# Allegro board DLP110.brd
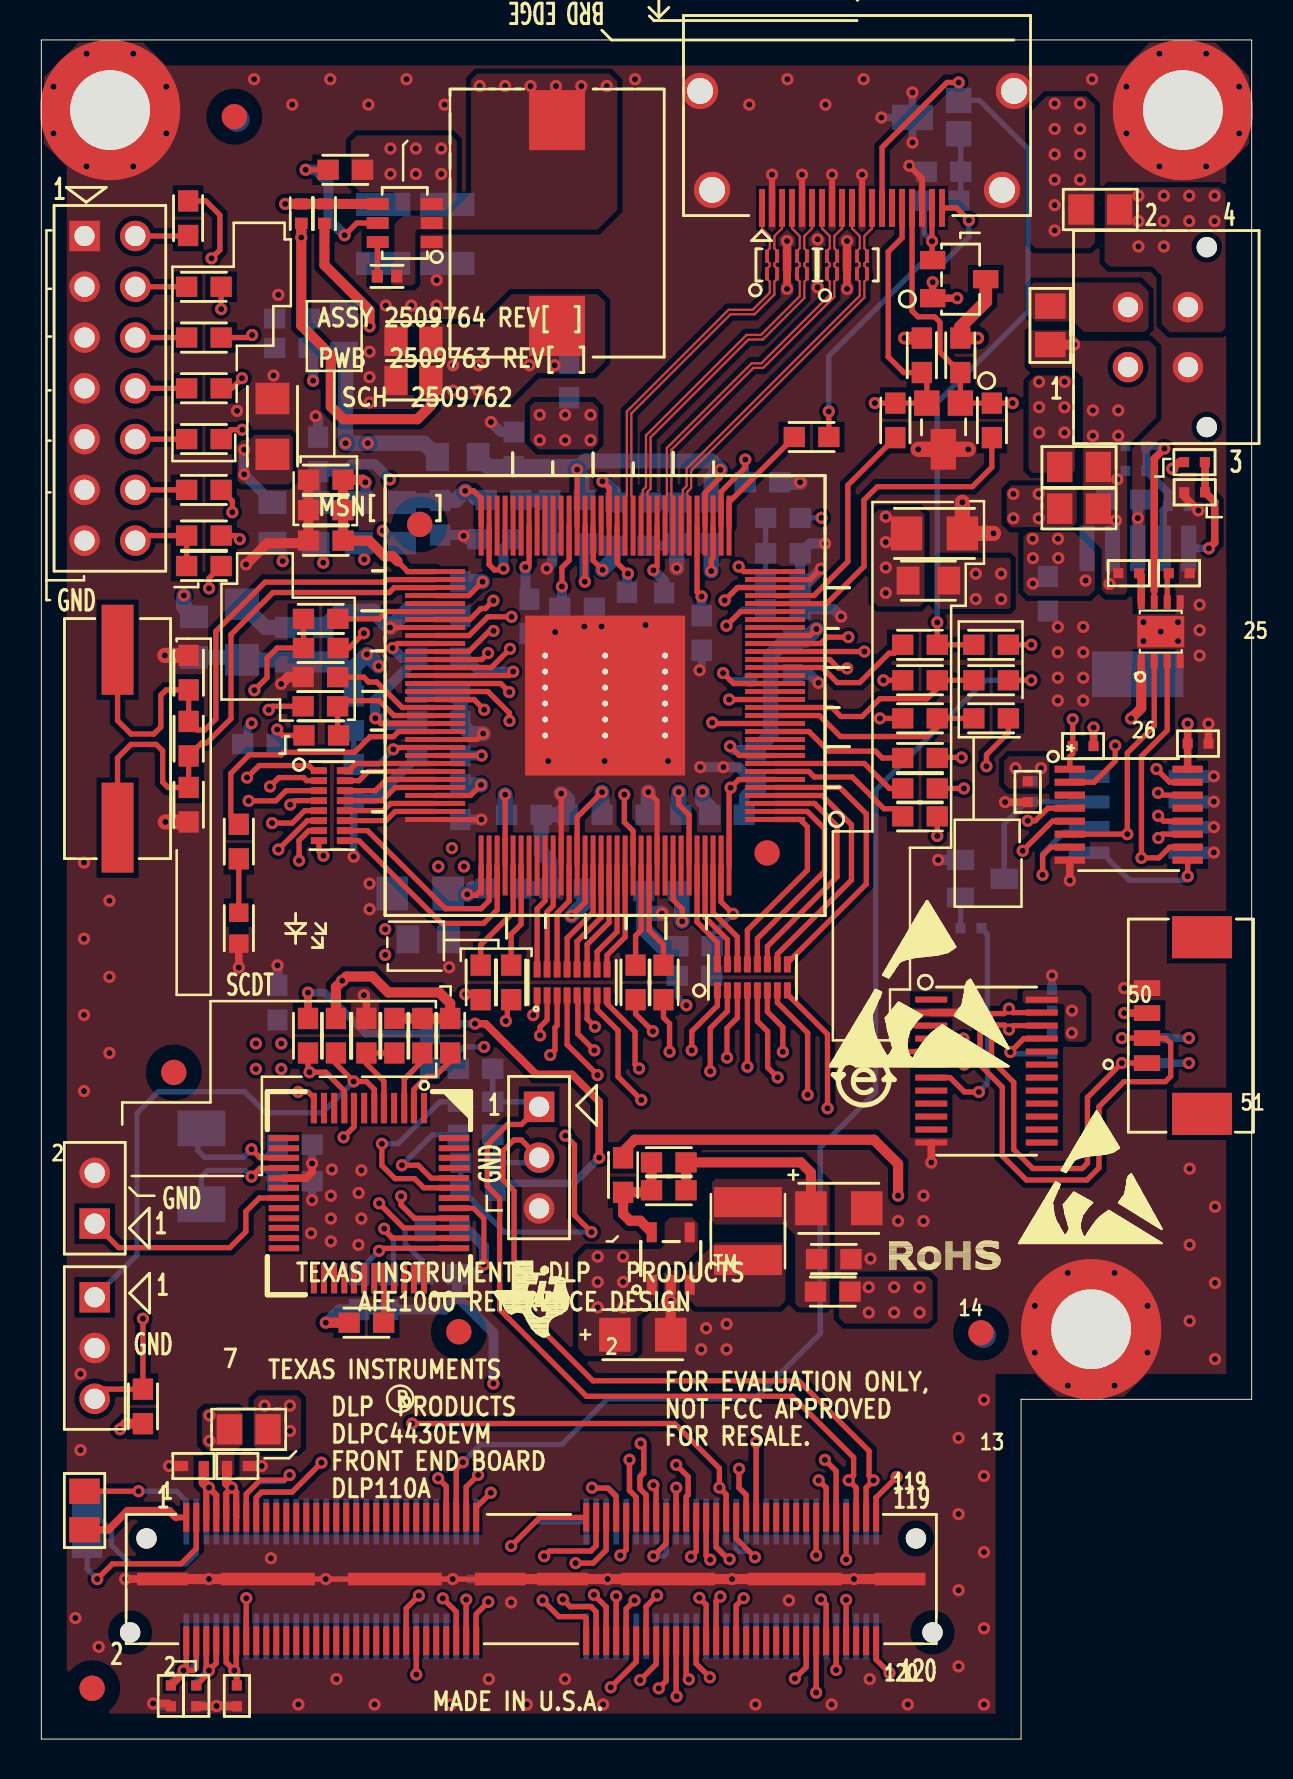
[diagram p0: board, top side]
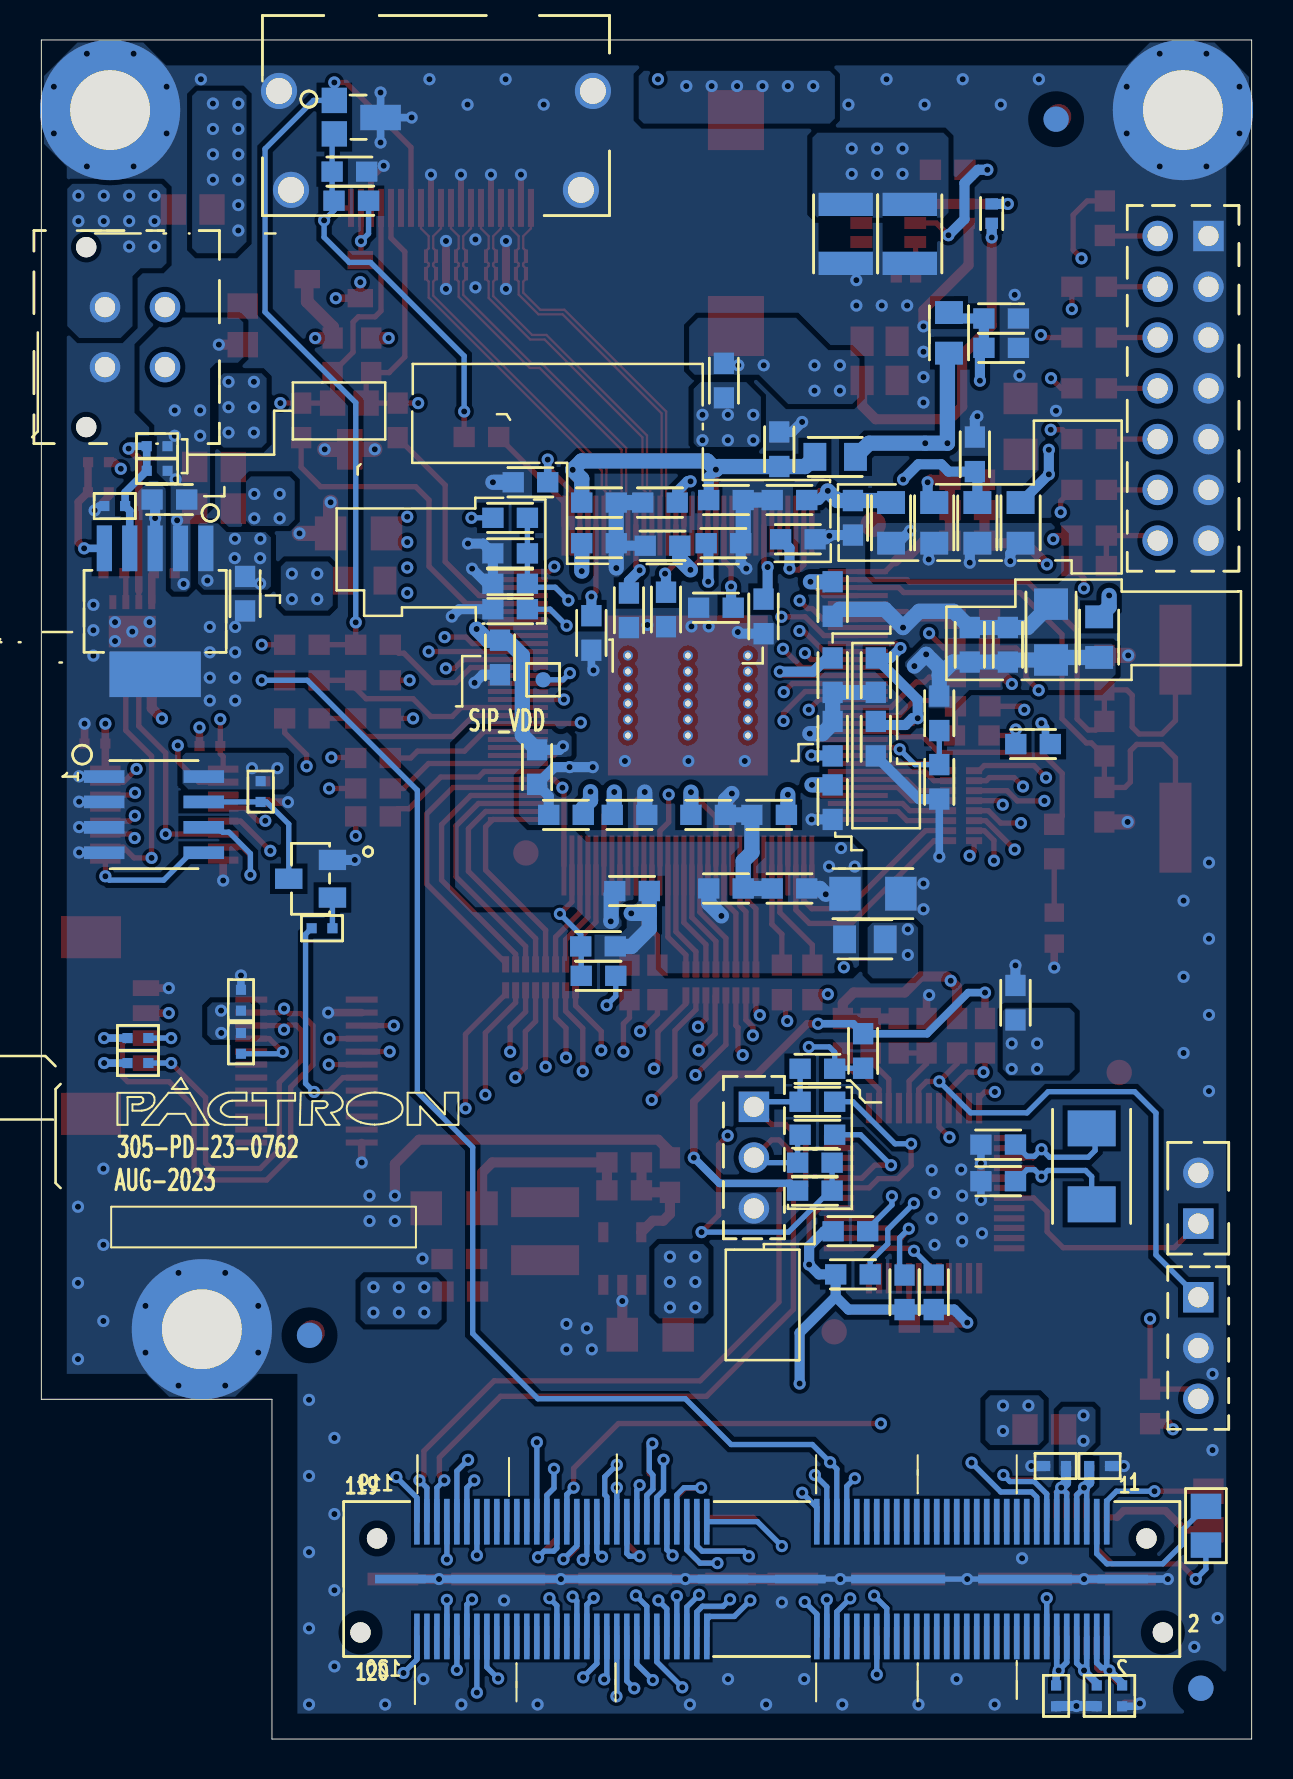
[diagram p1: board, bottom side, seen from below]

Outline 60.53 x 84.99 mm; copper layers: TOP, 02_GND1, 03_SIG1, 04_GND2, 05_SIG2, 06_PWR, 07_GND3, BOTTOM. Coordinates in mm from the lower left corner of the outline.
Outline path: 0,84.99 0,0 49,0 49,16.99 60.53,16.99 60.53,84.99 0,84.99

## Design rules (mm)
net group ALT_PWR: nets ALT_PWR ALT_PWR_MCONN
net group HSYNC: nets HSYNC P2_HSYNC
net group I2S0_DL0_CONN: nets I2S0_DL0_CONN N17213125
net group I2S1_DR1_CONN: nets I2S1_DR1_CONN N17213123
net group I2S_SCK_CONN: nets I2S_SCK_CONN N17213129
net group P1_A0: nets N17675272 P1_A0
net group P1_A1: nets N17675274 P1_A1
net group P1_B0: nets N18010978 P1_B0
net group P1_B1: nets N18010974 P1_B1
net group P1_FIELD: nets N17791476 P1_FIELD
net group P2_CLK: nets P2_CLK PCLK
net group P2_VSYNC: nets P2_VSYNC VSYNC
net group WS_DR0_CONN: nets N17213127 WS_DR0_CONN
net group CLOCK: nets N17176927 N17176943 XTAL1 XTAL2
net group GROUP_A: nets P1_ACTDATA
net group GROUP_B: nets AFE_RSTZ HAPS_CLK P1_HSYNC P1_VSYNC
net group HDMI: nets P1_A2 P1_A3 P1_A4 P1_A5 P1_A6 P1_A7 P1_A8 P1_A9 P1_B2 P1_B3 P1_B4 P1_B5 P1_B6 P1_B7 P1_B8 P1_B9 P1_C0 P1_C1 P1_C2 P1_C3 P1_C4 P1_C5 P1_C6 P1_C7 P1_C8 P1_C9
net group P1_A2: nets N17675276
net group P1_A3: nets N17675278
net group P1_A4: nets N17675280
net group P1_A5: nets N17675282
net group P1_A6: nets N17675284
net group P1_A7: nets N17675286
net group P1_A8: nets N17675288
net group P1_A9: nets N17675290
net group P1_B2: nets N18010926
net group P1_B3: nets N18010922
net group P1_B4: nets N18011121
net group P1_B5: nets N18011123
net group P1_B6: nets N18011125
net group P1_B7: nets N18011127
net group P1_B8: nets N18011129
net group P1_B9: nets N18011131
net group P1_C0: nets N18011517
net group P1_C1: nets N18011513
net group P1_C2: nets N18011465
net group P1_C3: nets N18011461
net group P1_C4: nets N18011660
net group P1_C5: nets N18011662
net group P1_C6: nets N18011664
net group P1_C7: nets N18011666
net group P1_C8: nets N18011668
net group P1_C9: nets N18011670
net group P3P3V_AFE: nets P3P3V_AFE_ADJ_A P3P3V_AFE_FB PCA9539_PU
net group P3P3V_AFE_EN: nets P3P3V_AFE_EN
net group POWER: nets HDMI_EDID_WP P1P2V_MAIN P1P8V_MAIN P2P5V_MAIN P3P3V_MAIN
net group RX_OVDD: nets N17741544

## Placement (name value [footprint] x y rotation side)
C3  0.1 uF  [CAP_0402]  57.85 49.79 180 top
C5  0.1 uF  [CAP_0402]  50.55 36.96 270 bottom
C17  18pF  [C0603]  7.37 53.34 270 top
C18  18pF  [C0603]  7.37 46.74 90 top
C34  0.1 uF  [CAP_0402]  7.6 13.66 180 top
C35  0.1 uF  [CAP_0402]  9.8 13.66 0 top
C36  0.1 uF  [CAP_0402]  6.48 2.16 270 top
C37  0.1 uF  [CAP_0402]  7.75 2.16 270 top
C38  0.1 uF  [CAP_0402]  9.78 2.16 270 top
C508  0.1 uF  [CAP_0402]  49.33 47.38 90 top
C605  2.2 uF  [CAP_0603]  50.34 57.29 270 bottom
C606  2.2 uF  [CAP_0603]  54.12 62 0 bottom
C607  0.01uF  [CAP_0402]  54.74 64.67 180 bottom
C608  0.1 uF  [CAP_0402]  57.68 62.36 0 top
C617  0.1 uF  [CAP_0402]  9.8 13.66 0 bottom
C618  0.1 uF  [CAP_0402]  7.6 13.66 180 bottom
C619  0.1 uF  [CAP_0402]  9.78 2.16 270 bottom
C620  0.1 uF  [CAP_0402]  7.75 2.16 270 bottom
C621  0.1 uF  [CAP_0402]  6.48 2.16 270 bottom
C623  10uF  [C1206]  30.08 20.22 0 top
C624  22uF  [C1206]  39.88 26.55 0 top
C625  0.1uF  [C0603]  39.63 24.01 0 top
C626  100pF  [C0603]  31.38 28.84 0 top
C628  NC  [C0603]  32.69 39.65 180 bottom
C629  10uF_10V_1206  [C1206]  10.03 55.37 90 bottom
C630  0.1uF  [C0603]  12.19 54.74 90 bottom
C631  0.1uF  [C0603]  14.1 54.74 90 bottom
C632  0.1uF  [C0603]  34.29 46.23 0 bottom
C633  0.1uF  [C0603]  20.95 46.86 270 bottom
C634  0.1uF  [C0603]  27.18 46.23 180 bottom
C635  0.1uF  [C0603]  20.95 57.02 270 bottom
C636  0.1uF  [C0603]  20.95 50.04 90 bottom
C637  0.1uF  [C0603]  20.95 53.21 270 bottom
C638  1nF  [C0603]  24.13 46.23 0 bottom
C639  1nF  [C0603]  31.11 46.23 180 bottom
C641  2.2uF  [C0603]  12.53 71.06 180 bottom
C642  0.1uF  [C0603]  12.53 69.59 180 bottom
C643  10uF_10V_1206  [C1206]  44.67 60.31 0 top
C644  0.1uF  [C0603]  22.69 60.01 180 bottom
C645  0.1uF  [C0603]  26.79 56.59 0 bottom
C646  1nF  [C0603]  29.29 56.5 270 bottom
C647  1nF  [C0603]  24.41 56.15 270 bottom
C648  2.2uF  [C0603]  32.64 61.85 180 bottom
C649  0.1uF  [C0603]  23.62 64.52 90 bottom
C650  0.1uF  [C0603]  26.29 61.98 180 bottom
C651  10uF_10V_1206  [C1206]  11.56 65.66 90 top
C652  0.1uF  [C0603]  36.07 62.87 0 bottom
C653  0.1uF  [C0603]  29.46 59.69 0 bottom
C654  0.1uF  [C0603]  31.14 56.46 270 bottom
C655  0.1uF  [C0603]  33.02 55.33 270 bottom
C660  2.2uF  [C0603]  32.64 59.82 180 bottom
C661  0.1uF  [C0603]  26.42 59.82 180 bottom
C662  0.1uF  [C0603]  13.84 64.26 90 bottom
C663  2.2uF  [C0603]  14.22 59.94 180 top
C664  0.1uF  [C0603]  14.22 61.47 180 top
C665  0.1uF  [C0603]  14.22 62.99 180 top
C666  10uF_10V_1206  [C1206]  18.94 42.29 180 bottom
C667  0.1uF  [C0603]  18.8 53.21 270 bottom
C668  0.1uF  [C0603]  18.8 50.04 270 bottom
C669  0.1uF  [C0603]  23.11 42.55 0 bottom
C670  0.1uF  [C0603]  30.99 42.42 180 bottom
C671  0.1uF  [C0603]  26.29 42.55 180 bottom
C672  0.1uF  [C0603]  35.74 48.62 270 bottom
C673  0.1uF  [C0603]  37.59 54.1 270 bottom
C676  2.2uF  [C0603]  23.11 61.98 0 bottom
C677  0.1uF  [C0603]  19.94 61.09 270 bottom
C678  0.1uF  [C0603]  29.59 61.85 0 bottom
C679  1nF  [C0603]  37.08 57.78 0 bottom
C680  22pF  [C0603]  12.67 27.9 0 bottom
C681  0.1uF  [C0603]  17.65 35.18 270 top
C682  22pF  [C0603]  12.67 29.73 0 bottom
C683  0.1uF  [C0603]  11.81 36.83 90 bottom
C796  0.1uF  [C0402]  17.29 73.17 180 top
C797  10 uF  [C1210]  17.09 75.29 90 bottom
C798  10 uF  [C1210]  20.3 75.29 90 bottom
C799  0.1uF  [C0402]  13 76.3 90 top
C800  22 uF  [C0805]  18.61 69.92 0 top
C801  22 uF  [C0805]  18.61 67.96 0 top
CN1  -  [10029449-111RLF]  40.79 84.99 180 top
D517  RClamp0502B  [SOT-523]  45.12 66.55 180 top
D518  BAV70  [SOT23B]  45.97 73.03 270 top
D519  RClamp0502B  [SOT-523]  45.6 81.13 270 bottom
D520  NC/ LED  [LED0603]  9.87 40.56 270 top
FB1  BBPY00201209600Y00  [FB0805]  7.63 55.12 0 bottom
FB2  BBPY00201209600Y00  [FB0805]  15.14 70.34 180 bottom
FB3  BBPY00201209600Y00  [FB0805]  44.36 57.95 90 top
FB4  BBPY00201209600Y00  [FB0805]  20.83 64.14 90 bottom
FB5  BBPY00201209600Y00  [FB0805]  11.56 60.83 180 bottom
FB6  BBPY00201209600Y00  [FB0805]  13.72 60.83 180 bottom
FB7  BBPY00201209600Y00  [FB0805]  15.88 60.83 180 bottom
FB8  BBPY00201209600Y00  [FB0805]  19.34 40 90 bottom
FB9  BBPY00201209600Y00  [FB0805]  18.03 60.83 180 bottom
J3  HEADER 7X2  [HEADER_7X2]  3.43 67.56 270 top
J6  -  [CONN_4]  55.3 35.69 90 top
J7  MOLEX 3MM  [3MM_4]  54.35 68.63 270 top
J9  conn_120_QTH  [QTH_120]  24.5 8 0 top
J500  conn_120_QTH  [QSH_120]  24.5 8 0 bottom
JP1  HEADER_1x2_A  [HEADER1X2_2_54]  2.67 27.05 90 top
JP2  HEADER 3  [HEADER3]  2.67 19.56 270 top
JP3  HEADER 3  [HEADER3]  24.89 29.08 270 top
L502  4.7uH  [3_6MMX3_8MM]  35.34 25.41 180 top
L503  2.2 uH  [IND-SRR1005_BOURNS]  25.79 75.83 270 top
MT1  MOUNTING HOLE  [MH276-157GND]  3.44 81.48 0 top
MT2  MOUNTING HOLE  [MH276-157GND]  57.09 81.48 0 top
MT3  MOUNTING HOLE  [MH276-157GND]  52.5 20.5 0 top
NOREF  -  []  60.53 84.99 0 top
NOREF#2  -  [unnamed#2]  20.88 20.37 90 top
NOREF#3  -  [unnamed#2]  9.65 81.15 0 top
NOREF#4  -  []  -10.16 -10.16 0 top
NOREF#5  -  []  0 0 0 top
NOREF#6  -  []  82.17 59.94 0 top
NOREF#7  -  []  0 0 0 top
NOREF#8  -  []  -10.16 93.98 0 top
NOREF#9  -  [unnamed#2]  2.54 2.54 0 top
NOREF#10  -  []  49 0 0 top
NOREF#11  -  []  60.53 16.99 0 top
NOREF#12  -  []  114.3 93.98 0 top
NOREF#13  -  []  60.53 84.99 0 top
NOREF#14  -  []  3.44 81.48 0 top
NOREF#15  -  [unnamed#2]  46.99 20.32 0 top
NOREF#16  -  [unnamed#2]  18.92 60.76 90 top
NOREF#17  -  [unnamed#2]  36.3 44.32 90 top
NOREF#18  -  []  -78.61 -53.59 0 top
NOREF#19  -  []  -11.35 6.5 0 top
NOREF#20  -  []  3.44 81.48 0 top
NOREF#21  -  [unnamed#2]  6.62 33.34 0 top
NOREF#22  -  []  228.37 36.27 0 top
NOREF#23  -  [unnamed#2]  2.54 2.54 180 bottom
NOREF#24  -  [unnamed#2]  47.12 20.19 180 bottom
NOREF#25  -  [unnamed#2]  9.78 81.03 180 bottom
Q500  2N2222  [SOT-23-3]  47.06 43.03 270 bottom
R1  22  [R0603]  8.13 60.2 0 top
R2  22  [R0603]  8.13 62.48 0 top
R3  22  [R0603]  8.13 65.02 0 top
R5  3K  [R0603]  37.08 56.52 0 bottom
R8  3.3K  [RES_0402]  50.55 34.8 270 bottom
R9  22  [R0603]  8.13 67.56 0 top
R10  22  [R0603]  8.13 70.1 0 top
R11  22  [R0603]  8.13 72.64 0 top
R15  3.3K  [RES_0402]  52.1 49.67 180 top
R18  22  [R0603]  29.72 37.85 270 top
R19  22  [R0603]  31.11 37.85 270 top
R20  22  [R0603]  21.97 37.85 270 top
R21  22  [R0603]  23.5 37.85 270 top
R29  1M  [R0603]  7.37 50.04 270 top
R30  22  [R0603]  43.94 46.15 0 top
R31  22  [R0603]  43.94 47.55 0 top
R32  22  [R0603]  47.5 52.96 0 top
R34  22  [R0603]  32.66 38.18 180 bottom
R38  0  [RES_0805]  10.37 15.49 0 top
R39  22  [R0603]  13.97 56.03 0 top
R47  10K  [RES_0402]  55.7 35.06 180 bottom
R48  10K  [RES_0402]  55.7 33.81 180 bottom
R50  0.01  [RES_0805]  51.89 61.55 180 top
R51  0  [RES_0805]  51.89 63.63 0 top
R52  113K  [RES_0402]  56.9 58.31 0 top
R53  200K  [RES_0402]  54.38 58.31 180 top
R54  0  [RES_0805]  50.46 70.71 270 top
R55  0  [RES_0805]  52.96 76.51 180 top
R56  0  [RES_0805]  2.16 11.43 90 top
R500  10K  [RES_0402]  46.49 40.56 180 bottom
R509  3.3K  [RES_0402]  49.56 47.39 270 bottom
R540  0  [R0603]  13.95 51.66 180 top
R541  1K  [R0603]  13.96 53.12 180 top
R542  0  [R0603]  14 50.2 180 top
R543  4.7K  [R0603]  15.62 47.88 90 bottom
R544  NC  [R0603]  15.62 51.31 270 bottom
R568  22  [R0603]  43.94 52.96 180 top
R569  22  [R0603]  47.5 51.05 0 top
R570  22  [R0603]  43.94 49.07 0 top
R571  NC  [R0603]  13.98 54.57 180 top
R572  22  [R0603]  43.94 51.05 180 top
R573  51K  [RES_0402]  54.74 63.44 180 bottom
R574  29.4K  [RES_0402]  56.86 61.68 0 bottom
R575  3.3K  [RES_0402]  57.67 63.87 0 top
R583  0  [RES_0805]  2.29 10.67 90 bottom
R584  10K  [R0603]  45.96 69.22 90 top
R585  10K  [R0603]  44.03 69.22 90 top
R586  30K  [R0603]  31.38 27.45 0 top
R588  30K  [R0603]  29.09 28.21 270 top
R589  33  [R0603]  42.71 65.96 270 top
R590  NC  [R0603]  45.03 76.95 0 bottom
R591  33  [R0603]  47.54 65.96 270 top
R592  100K  [R0603]  45.12 78.4 180 bottom
R593  10K  [R0603]  13.34 35.18 90 top
R594  NC/ 680  [R0603]  9.87 44.89 270 top
R595  22  [R0603]  38.52 65.13 180 top
R601  0  [R0603]  47.5 54.74 0 top
R602  0  [R0603]  43.94 54.74 0 top
R605  22  [R0603]  7.34 76.07 90 top
R606  NC  [R0603]  8.13 58.67 0 top
R607  33  [R0603]  21.84 28.83 0 bottom
R608  33  [R0603]  21.72 33.53 0 bottom
R609  4.7K  [R0603]  19.43 34.42 270 bottom
R610  4.7K  [R0603]  21.84 27.43 180 bottom
R611  1.5K  [R0603]  37.08 61.09 180 bottom
R612  3K  [R0603]  37.08 59.31 0 bottom
R614  NC  [R0603]  20.07 25.4 180 bottom
R615  33  [R0603]  21.72 30.23 0 bottom
R616  NC  [R0603]  17.36 22.35 90 bottom
R617  NC  [R0603]  15.9 22.35 90 bottom
R618  33  [R0603]  21.72 31.88 0 bottom
R619  NC  [R0603]  19.94 23.24 180 bottom
R620  NC  [R0603]  20.45 35.18 90 top
R621  NC  [R0603]  19.05 35.18 90 top
R622  4.7K  [R0603]  14.73 35.18 90 top
R623  4.7K  [R0603]  5.08 16.64 270 top
R624  4.7K  [R0603]  10.93 49.77 180 bottom
R625  1K  [R0603]  16.26 20.83 0 top
R628  10K  [R0603]  16.26 35.18 270 top
R629  0  [R0603]  39.58 22.38 0 top
R630  0  [R0603]  26.4 67.95 270 bottom
R633  5.76 K  [R0402]  13 76.3 90 bottom
R634  10 K  [R0402]  14.16 76.3 270 top
R635  0  [R0603]  15.2 78.5 0 top
RN1  RESARR_IS_8/SO  [RESARR_IS_8_SO]  14.53 46.69 270 top
RN2  RESARR_IS_8/SO  [RESARR_IS_8_SO]  26.54 37.85 0 top
RN4  RESARR_IS_8/SO  [RESARR_IS_8_SO]  35.56 38.1 0 top
TP1  TEST  [S-ICT30]  35.43 52.98 180 bottom
U7  74CB3T3253  [TSSOP_16]  54.38 46.24 270 top
U8  TCA9539  [TSSOP_24]  47.27 33.41 270 top
U14  MAX5418  [TDFN_8]  55.98 55.39 90 top
U500  24C02C  [SOIC_8]  54.89 46.24 270 bottom
U505  TPS73701  [SOT223_6]  54.84 56.41 0 bottom
U510  RClamp0524P  [SC-70_6L]  37.29 73.74 0 top
U511  RClamp0524P  [SC-70_6L]  40.29 73.74 0 top
U512  IT7831TS  [TSOT-25]  31.48 24.03 0 top
U516  IT6802  [LQFP-128_WITH_GND_PAD]  28.19 52.2 180 top
U517  8051_LQFP48  [LQFP-48]  16.38 27.3 180 top
U518  TPS564201  [TSOT23-6]  18.17 75.83 180 top
X1  27.000MHz  [SBX49SM]  3.81 50.04 270 top
Y-1  12.000MHz  [XTAL_HC49SMT]  8 28.65 270 bottom

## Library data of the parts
C3 = CAP NP: signal model: DEFAULT_CAPACITOR_1000pF_2_1
C5 C34-C38 C608 C617-C621 = CAP NP: signal model: DEFAULT_CAPACITOR_100000pF_2_1
C17 C18 C607 = CAP NP: signal model: DEFAULT_CAPACITOR_18pF_2_1
C508 C628-C639 C641-C655 C660-C673 C676-C679 = CAP NP
C605 C606 = CAP NP: signal model: DEFAULT_CAPACITOR_2.2e+06pF_2_1
C623 C796-C801 = C
C624 = CAP_0
C625 C626 C680-C683 = CAP NP_0
CN1 = HDMI_MHL Connector - SMT_1
D517 D519 = rclamp0502b_0
D518 = BAV70/SOT_0
D520 = LED
FB1-FB9 = FerritBead
J3 = HEADER 7X2
J6 = CONN_4
J7 = HDR_4
J9 J500 = conn_120_QTH: signal model: CONN_120_QTH_QTH_120_CONN_120_Q
JP1 = HEADER_1x2_A
JP2 JP3 = HEADER 3_0
L502 = INDUCTOR IRON_0.8mm
L503 = L
MT1-MT3 = Testpoint_0
Q500 = 2N2222
R1-R3 R9 R30 R31 R34 R568 R571 R572 = RESISTOR_0: signal model: DEFAULT_RESISTOR_33OHM_2_1
R5 R541 R586 R588-R593 R595 R611 R612 = R_2
R8 R575 = R: signal model: DEFAULT_RESISTOR_3300OHM_2_1
R10 R11 R32 R39 R540 R542 R569 R570 R584 R601 R602 R605-R610 R629 R630 R635 = RESISTOR_0
R15 R47 R48 R500 R509 R583 R633 R634 = R
R18-R20 = RESISTOR_0: signal model: 10
R21 = RESISTOR_0: signal model: 20
R29 = RESISTOR_2
R38 R51 R54-R56 = R: signal model: DEFAULT_RESISTOR_0.001OHM_2_1
R50 = R: signal model: DEFAULT_RESISTOR_0.01OHM_2_1
R52 = R: signal model: DEFAULT_RESISTOR_113000OHM_2_1
R53 = R: signal model: DEFAULT_RESISTOR_205000OHM_2_1
R543 R544 = R_2: signal model: DEFAULT_RESISTOR_3300OHM_2_1
R573 = RESISTOR: signal model: DEFAULT_RESISTOR_51000OHM_2_1
R574 = R: signal model: DEFAULT_RESISTOR_30100OHM_2_1
R585 = RESISTOR_1
R594 = R_1
R614-R625 R628 = R_3
RN1 RN2 RN4 = RESARR_IS_8/SO: signal model: RESNW_IS_1_RPACK_16_33_33
TP1 = TEST
U7 = 74CB3T3253
U8 = PCA9539
U14 = MAX5418
U500 = 24C02_0
U505 = TPS73701
U510 U511 = RClamp0514M
U512 = IT7831TS
U516 = IT6802_0
U517 = 8051_LQFP48
U518 = TPS564201
X1 = CRY_1: signal model: DEFAULT_RESISTOR_2.8322e+07OHM_4_1
Y-1 = CRYSTAL_0

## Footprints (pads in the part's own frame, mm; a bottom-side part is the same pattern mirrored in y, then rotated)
3_6MMX3_8MM
  rect 3.4x1.5 smd: 1(0,1.45) 2(0,-1.45)
3MM_4
  round 1.016 hole 1.016 unplated: (-6,3.94) (3,3.94)
  round 1.524 hole 1.016: 1(0,0) 2(-3,0) 3(0,3) 4(-3,3)
10029449-111RLF
  rect 0.3x1.9 smd: 1(4.75,8.4) 2(4.25,8.4) 3(3.75,8.4) 4(3.25,8.4) 5(2.75,8.4) 6(2.25,8.4) 7(1.75,8.4) 8(1.25,8.4) 9(0.75,8.4) 10(0.25,8.4) 11(-0.25,8.4) 12(-0.75,8.4) 13(-1.25,8.4) 14(-1.75,8.4) 15(-2.25,8.4) 16(-2.75,8.4) 17(-3.25,8.4) 18(-3.75,8.4) 19(-4.25,8.4)
  round 1.808 hole 1.3: 20(-7.25,7.5) 21(7.25,7.5) 22(-7.85,2.55) 23(7.85,2.55)
C0402
  rect 0.56x0.63 smd: 1(-0.485,0) 2(0.485,0)
C0603
  rect 1.067x1.016 smd: 1(-0.864,0) 2(0.864,0)
C0805
  rect 1.16x1.47 smd: 1(-0.875,0) 2(0.875,0)
C1206
  rect 1.575x1.7 smd: 1(-1.397,0) 2(1.397,0)
C1210
  rect 1.16x2.72 smd: 1(-1.475,0) 2(1.475,0)
CAP_0402
  rect 0.508x0.508 smd: 1(-0.521,0) 2(0.521,0)
CAP_0603
  rect 1.067x1.016 smd: 1(-0.864,0) 2(0.864,0)
CONN_4
  rect 2.108x2.997 smd: (-4.415,-2.75) (4.421,-2.75)
  rect 0.787x1.321 smd: 1(-1.875,0) 2(-0.625,0) 3(0.625,0) 4(1.875,0)
FB0805
  rect 1.397x1.143 smd: 1(0,1.016) 2(0,-1.016)
HEADER1X2_2_54
  rect 1.524x1.524 hole 1.016: 1(-1.27,0)
  round 1.524 hole 1.016: 2(1.27,0)
HEADER3
  rect 1.524x1.524 hole 1.016: 1(-2.54,0)
  round 1.524 hole 1.016: 2(0,0) 3(2.54,0)
HEADER_7X2
  rect 1.524x1.524 hole 1.016: 1(-7.62,-1.27)
  round 1.524 hole 1.016: 2(-7.62,1.27) 3(-5.08,-1.27) 4(-5.08,1.27) 5(-2.54,-1.27) 6(-2.54,1.27) 7(0,-1.27) 8(0,1.27) 9(2.54,-1.27) 10(2.54,1.27) 11(5.08,-1.27) 12(5.08,1.27) 13(7.62,-1.27) 14(7.62,1.27)
IND-SRR1005_BOURNS
  rect 3x2.8 smd: 1(-5.15,0) 2(5.15,0)
LED0603
  rect 0.92x0.97 smd: 1(-0.775,0) 2(0.775,0)
LQFP-48
  rect 0.305x1.524 smd: 1(-2.756,-4.255) 2(-2.248,-4.255) 3(-1.765,-4.255) 4(-1.257,-4.255) 5(-0.749,-4.255) 6(-0.267,-4.255) 7(0.241,-4.255) 8(0.749,-4.255) 9(1.232,-4.255) 10(1.74,-4.255) 11(2.248,-4.255) 12(2.756,-4.255) 25(2.756,4.255) 26(2.248,4.255) 27(1.74,4.255) 28(1.232,4.255) 29(0.749,4.255) 30(0.241,4.255) 31(-0.267,4.255) 32(-0.749,4.255) 33(-1.257,4.255) 34(-1.765,4.255) 35(-2.248,4.255) 36(-2.756,4.255)
  rect 1.524x0.305 smd: 13(4.255,-2.756) 14(4.255,-2.248) 15(4.255,-1.765) 16(4.255,-1.257) 17(4.255,-0.749) 18(4.255,-0.267) 19(4.255,0.241) 20(4.255,0.749) 21(4.255,1.257) 22(4.255,1.74) 23(4.255,2.248) 24(4.255,2.756) 37(-4.255,2.756) 38(-4.255,2.248) 39(-4.255,1.74) 40(-4.255,1.257) 41(-4.255,0.749) 42(-4.255,0.241) 43(-4.255,-0.267) 44(-4.255,-0.749) 45(-4.255,-1.257) 46(-4.255,-1.765) 47(-4.255,-2.248) 48(-4.255,-2.756)
LQFP-128_WITH_GND_PAD
  round 0.5 hole 0.3: (-3,2) (-3,1.2) (-3,0.4) (-3,-0.4) (-3,-1.2) (-3,-2) (0,2) (0,1.2) (0,0.4) (0,-0.4) (0,-1.2) (0,-2) (3,2) (3,1.2) (3,0.4) (3,-0.4) (3,-1.2) (3,-2)
  rect 3x0.25 smd: 1(-8.5,6.2) 2(-8.5,5.8) 3(-8.5,5.4) 4(-8.5,5) 5(-8.5,4.6) 6(-8.5,4.2) 7(-8.5,3.8) 8(-8.5,3.4) 9(-8.5,3) 10(-8.5,2.6) 11(-8.5,2.2) 12(-8.5,1.8) 13(-8.5,1.4) 14(-8.5,1) 15(-8.5,0.6) 16(-8.5,0.2) 17(-8.5,-0.2) 18(-8.5,-0.6) 19(-8.5,-1) 20(-8.5,-1.4) 21(-8.5,-1.8) 22(-8.5,-2.2) 23(-8.5,-2.6) 24(-8.5,-3) 25(-8.5,-3.4) 26(-8.5,-3.8) 27(-8.5,-4.2) 28(-8.5,-4.6) 29(-8.5,-5) 30(-8.5,-5.4) 31(-8.5,-5.8) 32(-8.5,-6.2) 65(8.5,-6.2) 66(8.5,-5.8) 67(8.5,-5.4) 68(8.5,-5) 69(8.5,-4.6) 70(8.5,-4.2) 71(8.5,-3.8) 72(8.5,-3.4) 73(8.5,-3) 74(8.5,-2.6) 75(8.5,-2.2) 76(8.5,-1.8) 77(8.5,-1.4) 78(8.5,-1) 79(8.5,-0.6) 80(8.5,-0.2) 81(8.5,0.2) 82(8.5,0.6) 83(8.5,1) 84(8.5,1.4) 85(8.5,1.8) 86(8.5,2.2) 87(8.5,2.6) 88(8.5,3) 89(8.5,3.4) 90(8.5,3.8) 91(8.5,4.2) 92(8.5,4.6) 93(8.5,5) 94(8.5,5.4) 95(8.5,5.8) 96(8.5,6.2)
  rect 0.25x3 smd: 33(-6.2,-8.5) 34(-5.8,-8.5) 35(-5.4,-8.5) 36(-5,-8.5) 37(-4.6,-8.5) 38(-4.2,-8.5) 39(-3.8,-8.5) 40(-3.4,-8.5) 41(-3,-8.5) 42(-2.6,-8.5) 43(-2.2,-8.5) 44(-1.8,-8.5) 45(-1.4,-8.5) 46(-1,-8.5) 47(-0.6,-8.5) 48(-0.2,-8.5) 49(0.2,-8.5) 50(0.6,-8.5) 51(1,-8.5) 52(1.4,-8.5) 53(1.8,-8.5) 54(2.2,-8.5) 55(2.6,-8.5) 56(3,-8.5) 57(3.4,-8.5) 58(3.8,-8.5) 59(4.2,-8.5) 60(4.6,-8.5) 61(5,-8.5) 62(5.4,-8.5) 63(5.8,-8.5) 64(6.2,-8.5) 97(6.2,8.5) 98(5.8,8.5) 99(5.4,8.5) 100(5,8.5) 101(4.6,8.5) 102(4.2,8.5) 103(3.8,8.5) 104(3.4,8.5) 105(3,8.5) 106(2.6,8.5) 107(2.2,8.5) 108(1.8,8.5) 109(1.4,8.5) 110(1,8.5) 111(0.6,8.5) 112(0.2,8.5) 113(-0.2,8.5) 114(-0.6,8.5) 115(-1,8.5) 116(-1.4,8.5) 117(-1.8,8.5) 118(-2.2,8.5) 119(-2.6,8.5) 120(-3,8.5) 121(-3.4,8.5) 122(-3.8,8.5) 123(-4.2,8.5) 124(-4.6,8.5) 125(-5,8.5) 126(-5.4,8.5) 127(-5.8,8.5) 128(-6.2,8.5)
  rect 8x8 smd: 129(0,0)
MH276-157GND
  round 7.01 hole 3.988: 1(0,0)
QSH_120
  round 1.016 hole 1.016 unplated: (-20.06,2.67) (20.07,2.67)
  rect 0.279x2.286 smd: 1(-17.25,-2.87) 2(-17.25,2.87) 3(-16.75,-2.87) 4(-16.75,2.87) 5(-16.25,-2.87) 6(-16.25,2.87) 7(-15.75,-2.87) 8(-15.75,2.87) 9(-15.25,-2.87) 10(-15.25,2.87) 11(-14.75,-2.87) 12(-14.75,2.87) 13(-14.25,-2.87) 14(-14.25,2.87) 15(-13.75,-2.87) 16(-13.75,2.87) 17(-13.25,-2.87) 18(-13.25,2.87) 19(-12.75,-2.87) 20(-12.75,2.87) 21(-12.25,-2.87) 22(-12.25,2.87) 23(-11.75,-2.87) 24(-11.75,2.87) 25(-11.25,-2.87) 26(-11.25,2.87) 27(-10.75,-2.87) 28(-10.75,2.87) 29(-10.25,-2.87) 30(-10.25,2.87) 31(-9.75,-2.87) 32(-9.75,2.87) 33(-9.25,-2.87) 34(-9.25,2.87) 35(-8.75,-2.87) 36(-8.75,2.87) 37(-8.25,-2.87) 38(-8.25,2.87) 39(-7.75,-2.87) 40(-7.75,2.87) 41(-7.25,-2.87) 42(-7.25,2.87) 43(-6.75,-2.87) 44(-6.75,2.87) 45(-6.25,-2.87) 46(-6.25,2.87) 47(-5.75,-2.87) 48(-5.75,2.87) 49(-5.25,-2.87) 50(-5.25,2.87) 51(-4.75,-2.87) 52(-4.75,2.87) 53(-4.25,-2.87) 54(-4.25,2.87) 55(-3.75,-2.87) 56(-3.75,2.87) 57(-3.25,-2.87) 58(-3.25,2.87) 59(-2.75,-2.87) 60(-2.75,2.87) 61(2.75,-2.87) 62(2.75,2.87) 63(3.25,-2.87) 64(3.25,2.87) 65(3.75,-2.87) 66(3.75,2.87) 67(4.25,-2.87) 68(4.25,2.87) 69(4.75,-2.87) 70(4.75,2.87) 71(5.25,-2.87) 72(5.25,2.87) 73(5.75,-2.87) 74(5.75,2.87) 75(6.25,-2.87) 76(6.25,2.87) 77(6.75,-2.87) 78(6.75,2.87) 79(7.25,-2.87) 80(7.25,2.87) 81(7.75,-2.87) 82(7.75,2.87) 83(8.25,-2.87) 84(8.25,2.87) 85(8.75,-2.87) 86(8.75,2.87) 87(9.25,-2.87) 88(9.25,2.87) 89(9.75,-2.87) 90(9.75,2.87) 91(10.25,-2.87) 92(10.25,2.87) 93(10.75,-2.87) 94(10.75,2.87) 95(11.25,-2.87) 96(11.25,2.87) 97(11.75,-2.87) 98(11.75,2.87) 99(12.25,-2.87) 100(12.25,2.87) 101(12.75,-2.87) 102(12.75,2.87) 103(13.25,-2.87) 104(13.25,2.87) 105(13.75,-2.87) 106(13.75,2.87) 107(14.25,-2.87) 108(14.25,2.87) 109(14.75,-2.87) 110(14.75,2.87) 111(15.25,-2.87) 112(15.25,2.87) 113(15.75,-2.87) 114(15.75,2.87) 115(16.25,-2.87) 116(16.25,2.87) 117(16.75,-2.87) 118(16.75,2.87) 119(17.25,-2.87) 120(17.25,2.87)
  rect 2.54x0.432 smd: G1(-18.06,0) G4(-1.93,0) G5(1.94,0) G8(18.07,0)
  rect 4.699x0.432 smd: G2(-13.17,0) G3(-6.82,0) G6(6.83,0) G7(13.18,0)
QTH_120
  round 1.016 hole 1.016 unplated: (-19.239,2.032) (19.242,2.032)
  rect 0.305x1.448 smd: 1(-17.25,3.086) 2(-17.25,-3.086) 3(-16.75,3.086) 4(-16.75,-3.086) 5(-16.25,3.086) 6(-16.25,-3.086) 7(-15.75,3.086) 8(-15.75,-3.086) 9(-15.25,3.086) 10(-15.25,-3.086) 11(-14.75,3.086) 12(-14.75,-3.086) 13(-14.25,3.086) 14(-14.25,-3.086) 15(-13.75,3.086) 16(-13.75,-3.086) 17(-13.25,3.086) 18(-13.25,-3.086) 19(-12.75,3.086) 20(-12.75,-3.086) 21(-12.25,3.086) 22(-12.25,-3.086) 23(-11.75,3.086) 24(-11.75,-3.086) 25(-11.25,3.086) 26(-11.25,-3.086) 27(-10.75,3.086) 28(-10.75,-3.086) 29(-10.25,3.086) 30(-10.25,-3.086) 31(-9.75,3.086) 32(-9.75,-3.086) 33(-9.25,3.086) 34(-9.25,-3.086) 35(-8.75,3.086) 36(-8.75,-3.086) 37(-8.25,3.086) 38(-8.25,-3.086) 39(-7.75,3.086) 40(-7.75,-3.086) 41(-7.25,3.086) 42(-7.25,-3.086) 43(-6.75,3.086) 44(-6.75,-3.086) 45(-6.25,3.086) 46(-6.25,-3.086) 47(-5.75,3.086) 48(-5.75,-3.086) 49(-5.25,3.086) 50(-5.25,-3.086) 51(-4.75,3.086) 52(-4.75,-3.086) 53(-4.25,3.086) 54(-4.25,-3.086) 55(-3.75,3.086) 56(-3.75,-3.086) 57(-3.25,3.086) 58(-3.25,-3.086) 59(-2.75,3.086) 60(-2.75,-3.086) 61(2.75,3.086) 62(2.75,-3.086) 63(3.25,3.086) 64(3.25,-3.086) 65(3.75,3.086) 66(3.75,-3.086) 67(4.25,3.086) 68(4.25,-3.086) 69(4.75,3.086) 70(4.75,-3.086) 71(5.25,3.086) 72(5.25,-3.086) 73(5.75,3.086) 74(5.75,-3.086) 75(6.25,3.086) 76(6.25,-3.086) 77(6.75,3.086) 78(6.75,-3.086) 79(7.25,3.086) 80(7.25,-3.086) 81(7.75,3.086) 82(7.75,-3.086) 83(8.25,3.086) 84(8.25,-3.086) 85(8.75,3.086) 86(8.75,-3.086) 87(9.25,3.086) 88(9.25,-3.086) 89(9.75,3.086) 90(9.75,-3.086) 91(10.25,3.086) 92(10.25,-3.086) 93(10.75,3.086) 94(10.75,-3.086) 95(11.25,3.086) 96(11.25,-3.086) 97(11.75,3.086) 98(11.75,-3.086) 99(12.25,3.086) 100(12.25,-3.086) 101(12.75,3.086) 102(12.75,-3.086) 103(13.25,3.086) 104(13.25,-3.086) 105(13.75,3.086) 106(13.75,-3.086) 107(14.25,3.086) 108(14.25,-3.086) 109(14.75,3.086) 110(14.75,-3.086) 111(15.25,3.086) 112(15.25,-3.086) 113(15.75,3.086) 114(15.75,-3.086) 115(16.25,3.086) 116(16.25,-3.086) 117(16.75,3.086) 118(16.75,-3.086) 119(17.25,3.086) 120(17.25,-3.086)
  rect 2.54x0.635 smd: G1(-18.44,0) G4(-1.55,0) G5(1.56,0) G8(18.45,0)
  rect 4.699x0.635 smd: G2(-13.17,0) G3(-6.82,0) G6(6.83,0) G7(13.18,0)
R0402
  rect 0.56x0.63 smd: 1(-0.485,0) 2(0.485,0)
R0603
  rect 1.067x1.016 smd: 1(-0.864,0) 2(0.864,0)
RES_0402
  rect 0.508x0.508 smd: 1(-0.521,0) 2(0.521,0)
RES_0805
  rect 1.27x1.524 smd: 1(-0.965,0) 2(0.965,0)
RESARR_IS_8_SO
  rect 0.35x0.808 smd: 1(-1.75,-0.65) 2(-1.25,-0.65) 3(-0.75,-0.65) 4(-0.25,-0.65) 5(0.25,-0.65) 6(0.75,-0.65) 7(1.25,-0.65) 8(1.75,-0.65) 9(1.75,0.65) 10(1.25,0.65) 11(0.75,0.65) 12(0.25,0.65) 13(-0.25,0.65) 14(-0.75,0.65) 15(-1.25,0.65) 16(-1.75,0.65)
S-ICT30
  round 0.762 smd: 1(0,0)
SBX49SM
  rect 4.5x1.6 smd: 1(-4.45,0) 2(4.45,0)
SC-70_6L
  rect 0.2x0.675 smd: 1(-1,-0.437) 2(-0.5,-0.437) 4(0.5,-0.437) 5(1,-0.437) 6(1,0.437) 7(0.5,0.437) 9(-0.5,0.437) 10(-1,0.437)
  rect 0.4x1.55 smd: 3(0,0)
  rect 0.4x0.675 smd: 8(0,0.437)
SOIC_8
  rect 0.635x2.032 smd: 1(-1.905,-2.489) 2(-0.635,-2.489) 3(0.635,-2.489) 4(1.905,-2.489) 5(1.905,2.489) 6(0.635,2.489) 7(-0.635,2.489) 8(-1.905,2.489)
SOT23B
  rect 0.914x1.27 smd: 1(0.953,-1.397) 2(-0.953,-1.397) 3(0,1.257)
SOT223_6
  rect 0.762x2.286 smd: 1(-2.54,-3.15) 2(-1.27,-3.15) 3(0,-3.15) 4(1.27,-3.15) 5(2.54,-3.15)
  rect 4.572x2.286 smd: 6(0,3.15)
SOT-23-3
  rect 1.016x1.372 smd: 1(-0.94,1.092) 2(0.94,1.092) 3(0,-1.092)
SOT-523
  rect 1.27x1.27 smd: 1(-0.838,-0.279) 2(0.838,-0.279)
  rect 1.27x2.032 smd: 3(0.017,2.032)
TDFN_8
  rect 0.7x0.35 smd: 1(-1.475,0.975) 2(-1.475,0.325) 3(-1.475,-0.325) 4(-1.475,-0.975) 5(1.475,-0.975) 6(1.475,-0.325) 7(1.475,0.325) 8(1.475,0.975)
  rect 1.58x2.35 smd: 9(0,0)
TSOT23-6
  rect 1.1x0.6 smd: 1(-1.35,0.95) 2(-1.35,0) 3(-1.35,-0.95) 4(1.35,-0.95) 5(1.35,0) 6(1.35,0.95)
TSOT-25
  rect 0.51x1 smd: 1(-0.95,-1.315) 2(0,-1.315) 3(0.95,-1.315) 4(0.95,1.315) 5(-0.95,1.315)
TSSOP_16
  rect 0.356x1.524 smd: 1(-2.276,-2.946) 2(-1.626,-2.946) 3(-0.975,-2.946) 4(-0.325,-2.946) 5(0.325,-2.946) 6(0.975,-2.946) 7(1.626,-2.946) 8(2.276,-2.946) 9(2.276,2.946) 10(1.626,2.946) 11(0.975,2.946) 12(0.325,2.946) 13(-0.325,2.946) 14(-0.975,2.946) 15(-1.626,2.946) 16(-2.276,2.946)
TSSOP_24
  rect 0.305x1.6 smd: 1(-3.575,-2.763) 2(-2.925,-2.763) 3(-2.275,-2.763) 4(-1.625,-2.763) 5(-0.975,-2.763) 6(-0.325,-2.763) 7(0.325,-2.763) 8(0.975,-2.763) 9(1.625,-2.763) 10(2.275,-2.763) 11(2.925,-2.763) 12(3.575,-2.763) 13(3.575,2.763) 14(2.925,2.763) 15(2.275,2.763) 16(1.625,2.763) 17(0.975,2.763) 18(0.325,2.763) 19(-0.325,2.763) 20(-0.975,2.763) 21(-1.625,2.763) 22(-2.275,2.763) 23(-2.925,2.763) 24(-3.575,2.763)
unnamed#2
  round 1.27 smd: (0,0)
XTAL_HC49SMT
  rect 1.8x2.4 smd: 1(-1.9,0) 2(1.9,0)

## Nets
GND: C3.1 C5.1 C17.1 C18.1 C34.2 C35.2 C36.2 C37.2 C38.2 C508.1 C605.2 C606.2 C608.1 C617.2 C618.2 C619.2 C620.2 C621.2 C623.2 C624.2 C625.2 C628.2 C629.2 C630.2 C631.2 C632.2 C633.2 C634.2 C635.2 C636.2 C637.2 C638.2 C639.2 C641.2 C642.2 C643.2 C644.2 C645.2 C646.2 C647.2 C648.2 C649.2 C650.2 C651.2 C652.2 C653.2 C654.2 C655.2 C660.2 C661.2 C662.2 C663.2 C664.2 C665.2 C666.2 C667.2 C668.2 C669.2 C670.2 C671.2 C672.2 C673.2 C676.2 C677.2 C678.2 C679.2 C680.2 C682.2 C683.2 C797.1 C798.1 C800.1 C801.1 CN1.2(SHIELD/CD_SENSE) CN1.5(D1 SHIELD) CN1.8(D0 SHIELD) CN1.11(CK SHIELD) CN1.17(GND) CN1.20(SHELL1) CN1.21(SHELL2) CN1.22(SHELL3) CN1.23(SHELL4) D517.3 D519.3 D520.2(CATHODE) J3.1 J3.3 J3.5 J3.7 J3.9 J3.11 J3.13 J6.4 J7.1 J7.3 J9.G1 J9.G2 J9.G3 J9.G4 J9.G5 J9.G6 J9.G7 J9.G8 J500.G1 J500.G2 J500.G3 J500.G4 J500.G5 J500.G6 J500.G7 J500.G8 JP1.2 JP2.2 JP3.3 MT1.1 MT2.1 MT3.1 Q500.1(EMITTER) R5.2 R52.2 R541.2 R543.1 R574.2 R588.1 R592.2 R612.2 R628.1 R634.2 U7.8(GND) U8.2(A1) U8.12(GND) U14.4(A0) U14.5(GND) U14.9(PAD) U500.1(A0) U500.2(A1) U500.3(A2) U500.4(VSS) U505.3(GND_3) U505.6(GND_6) U510.3 U510.8 U511.3 U511.8 U512.2(GND) U516.31(CDSENSE) U516.72(IVSS12_1) U516.86(OVSS1) U516.96(IVSS12_2) U516.107(OVSS2) U516.119(IVSS12_3) U516.129(EXPOSED GND PAD) U517.17(VSS) U518.1(GND)
P5V: C605.1 C623.1 C797.2 C798.2 D518.1(A2) R38.2 R55.2 R575.1 R635.2 U14.1(VDD) U505.1(IN) U512.1(EN) U512.4(VIN) U518.3(VIN)
P5V_HDMI0: C508.2 D518.3(K) R509.1 R584.2 R585.2 U500.8(VCC)
P5V_LAB: J7.4 R55.1
P5V_MAIN: C35.1 C617.1 J9.9(A5) J9.11(A6) J500.9(A5) J500.11(A6) R38.1
51_SCL: JP2.1 R622.1 U517.6(P3.0/RXD)
51_SDA: JP2.3 R623.1 U517.8(P3.1/TXD)
AFE_RSTZ: J9.108(B54) J500.108(B54) R542.2 R624.1 U8.3(RESETZ) U517.12(P3.5/T1)
ALT_PWR: J9.1(A1) R56.1
ALT_PWR2: J9.3(A2) R583.1
ALT_PWR2_MCONN: J500.3(A2) R583.2
ALT_PWR_MCONN: J500.1(A1) R56.2
BUS_SELECT: J9.89(A45) J500.89(A45) R540.2
CEC: CN1.13(CE REMOTE) D519.1 R601.1 R602.2
DDCSCL0: R589.2 U516.29(DDCSCL0)
DDCSDA0: R591.2 U516.28(DDCSDA0)
DE: R570.1 U516.12(DE)
HAPS_CLK: J9.119(A60) J500.119(A60)
HDMI_0_VCC5: CN1.18(+5V) D518.2(A1) R590.1 R611.1
HDMI_CEC: J9.13(A7) J500.13(A7) R601.2
HDMI_DDC_CI_OEZ: R15.2 U7.1(1\O\E\) U7.15(2\O\E\) U8.6(P02)
HDMI_DDC_CI_S0: U7.14(S0) U8.4(P00)
HDMI_DDC_CI_S1: U7.2(S1) U8.5(P01)
HDMI_EDID_WEZ: R500.1 U8.7(P03)
HDMI_EDID_WP: Q500.3(COLLECTOR) R509.2 U500.7(WP)
HDMI_INT: J9.91(A46) J500.91(A46) R593.1 U516.21(INT#) U517.9(P3.2/I\N\T\0\)
HSYNC: R569.1 R572.1 U516.14(HSYNC)
I2S0_DL0_CONN: J3.10 R3.1
I2S1_DR1_CONN: J3.8 R9.1
I2S2_DL1_CONN: J3.6 R10.1
I2S3_DR2_CONN: J3.4 R11.1
I2S_SCK_CONN: J3.14 R1.1 R606.1
NC1: J9.48(B24) J500.48(B24)
NC2: J9.106(B53) J500.106(B53)
NC3: J9.107(A54) J500.107(A54)
NC4: J9.109(A55) J500.109(A55)
NC5: J9.110(B55) J500.110(B55)
NC6: J9.111(A56) J500.111(A56)
NC7: J9.112(B56) J500.112(B56)
NC8: J9.120(B60) J500.120(B60)
P0.0: R614.2 U517.40(P0.0/AD0)
P0.1: R619.2 U517.39(P0.1/AD1)
P0.2: R616.2 U517.38(P0.2/AD2)
P0.3: R617.2 U517.37(P0.3/AD3)
P1_A0: J9.65(A33) J500.65(A33) R21.2
P1_A1: J9.64(B32) J500.64(B32) R20.2
P1_A2: J9.63(A32) J500.63(A32) RN1.8
P1_A3: J9.62(B31) J500.62(B31) RN1.7
P1_A4: J9.61(A31) J500.61(A31) RN1.6
P1_A5: J9.60(B30) J500.60(B30) RN1.5
P1_A6: J9.59(A30) J500.59(A30) RN1.4
P1_A7: J9.58(B29) J500.58(B29) RN1.3
P1_A8: J9.57(A29) J500.57(A29) RN1.2
P1_A9: J9.56(B28) J500.56(B28) RN1.1
P1_ACTDATA: J9.87(A44) J500.87(A44) R570.2
P1_B0: J9.75(A38) J500.75(A38) R19.2
P1_B1: J9.74(B37) J500.74(B37) R18.2
P1_B2: J9.73(A37) J500.73(A37) RN2.8
P1_B3: J9.72(B36) J500.72(B36) RN2.7
P1_B4: J9.71(A36) J500.71(A36) RN2.6
P1_B5: J9.70(B35) J500.70(B35) RN2.5
P1_B6: J9.69(A35) J500.69(A35) RN2.4
P1_B7: J9.68(B34) J500.68(B34) RN2.3
P1_B8: J9.67(A34) J500.67(A34) RN2.2
P1_B9: J9.66(B33) J500.66(B33) RN2.1
P1_C0: J9.85(A43) J500.85(A43) R31.2
P1_C1: J9.84(B42) J500.84(B42) R30.2
P1_C2: J9.83(A42) J500.83(A42) RN4.8
P1_C3: J9.82(B41) J500.82(B41) RN4.7
P1_C4: J9.81(A41) J500.81(A41) RN4.6
P1_C5: J9.80(B40) J500.80(B40) RN4.5
P1_C6: J9.79(A40) J500.79(A40) RN4.4
P1_C7: J9.78(B39) J500.78(B39) RN4.3
P1_C8: J9.77(A39) J500.77(A39) RN4.2
P1_C9: J9.76(B38) J500.76(B38) RN4.1
P1_FIELD: J9.88(B44) J500.88(B44) R39.1 R571.2
P1_HSYNC: J9.86(B43) J500.86(B43) R569.2
P1_VSYNC: J9.55(A28) J500.55(A28) R32.2
P1P2V_MAIN: C36.1 C621.1 J9.2(B1) J9.4(B2) J500.2(B1) J500.4(B2)
P1P8V_MAIN: C37.1 C620.1 J9.6(B3) J9.8(B4) J500.6(B3) J500.8(B4)
P2.0: JP1.1 U517.19(P2.0/A8)
P2_CLK: J9.14(B7) J500.14(B7) R34.2
P2_HSYNC: J9.46(B23) J500.46(B23) R572.2
P2_VSYNC: J9.15(A8) J500.15(A8) R568.2
P2P5V_MAIN: C38.1 C619.1 J9.10(B5) J9.12(B6) J500.10(B5) J500.12(B6)
P3P3V_AFE: C3.2 C5.2 J6.3 R8.1 R15.1 R47.1 R48.1 R50.2 U7.16(VCC) U8.24(P3P3V)
P3P3V_AFE_ADJ_A: R53.1 U14.8(H)
P3P3V_AFE_ADJ_B: R52.1 U14.6(L)
P3P3V_AFE_EN: C608.2 R575.2 U505.5(EN)
P3P3V_AFE_FB: C607.1 R573.1 R574.1 U14.7(W) U505.4(FB)
P3P3V_ITE: C681.1 C683.1 FB1.2 FB2.2 FB3.2 FB4.2 R51.1 R614.1 R616.1 R617.1 R619.1 R620.2 R621.2 R622.2 R623.2 R624.2 R625.1 U517.41(VCC)
P3P3V_LAB: J7.2 R54.1
P3P3V_LAB_RES: C606.1 C607.2 R50.1 R51.2 R53.2 R54.2 R573.2 U505.2(OUT)
P3P3V_MAIN: C34.1 C618.1 J9.5(A3) J9.7(A4) J500.5(A3) J500.7(A4)
PCA9539_PU: R8.2 U8.21(A0)
PCLK: C628.1 R34.1 U516.127(PCLK)
PCSCL: R608.1 R609.2 U516.23(PCSCL)
PCSDA: R607.1 R610.2 U516.22(PCSDA)
R0X0M: CN1.9(D0-/MHL-) U511.2 U511.9 U516.40(P0_RX0N)
R0X0P: CN1.7(D0+/MHL+) U511.1 U511.10 U516.41(P0_RX0P)
R0X1M: CN1.6(D1-) U510.5 U510.6 U516.43(P0_RX1N)
R0X1P: CN1.4(D1+) U510.4 U510.7 U516.44(P0_RX1P)
R0X2M: CN1.3(D2-) U510.2 U510.9 U516.45(P0_RX2N)
R0X2P: CN1.1(D2+) U510.1 U510.10 U516.46(P0_RX2P)
R0XCM: CN1.12(CK-) U511.5 U511.6 U516.38(P0_RXCN)
R0XCP: CN1.10(CK+) U511.4 U511.7 U516.39(P0_RXCP)
RX_1V2: FB5.2 FB6.2 FB7.2 FB8.2 FB9.2 R629.2 R630.2
RX_APVDD12: C663.1 C664.1 C665.1 FB7.1 U516.65(APVDD12)
RX_AVCC12: C651.1 C652.1 C653.1 FB5.1 U516.34(AVCC12_1) U516.50(AVCC12_2)
RX_AVCC33: C643.1 C644.1 C645.1 C646.1 C647.1 C654.1 C655.1 FB3.1 U516.37(AVCC33_1) U516.42(AVCC33_2) U516.47(AVCC33_3) U516.53(AVCC33_4) U516.58(AVCC33_5) U516.63(APVCC33)
RX_DVDD12: C676.1 C677.1 C678.1 FB9.1 U516.48(DVDD12_1) U516.64(DVDD12_2)
RX_HPD0: CN1.19(HPD/CBUS) D519.2 R590.2 R592.1 R595.1
RX_IVDD12: C666.1 C667.1 C668.1 C669.1 C670.1 C671.1 C672.1 C673.1 FB8.1 U516.9(IVDD12_1) U516.24(IVDD12_2) U516.74(IVDD12_3) U516.84(IVDD12_7) U516.97(IVDD12_4) U516.110(IVDD12_5) U516.121(IVDD12_6)
RX_OVDD: C629.1 C630.1 C631.1 C632.1 C633.1 C634.1 C635.1 C636.1 C637.1 C638.1 C639.1 FB1.1 R544.1 U516.6(OVDD11) U516.13(OVDD8) U516.68(OVDD1) U516.78(OVDD2) U516.88(OVDD3) U516.93(OVDD4) U516.100(OVDD5) U516.109(OVDD6) U516.116(OVDD7) U516.123(OVDD9) U516.128(OVDD10)
RX_OVDD33: C641.1 C642.1 FB2.1 R593.2 R609.1 R610.1 U516.32(OVDD33)
RX_PVCC12: C660.1 C661.1 C662.1 FB6.1 U516.35(PVCC12_2) U516.51(PVCC12_1)
RX_PVCC33: C648.1 C649.1 C650.1 FB4.1 U516.36(PVCC33_1) U516.52(PVCC33_2)
SCL_0: J6.1 J9.115(A58) J500.115(A58) JP3.1 R48.2 R608.2 R618.2 U7.6(1B1) U8.22(SCL) U14.2(SCL)
SCL_DDC_CI_1: J9.95(A48) J500.95(A48) U7.5(1B2)
SCL_DDC_CI_2: J9.113(A57) J500.113(A57) U7.4(1B3)
SCL_HDMI0_DDC_CI: CN1.15(DDC CLK/CD_P_UP) D517.2 R585.1 R589.1 U7.7(1A) U500.6(SCL)
SDA_0: J6.2 J9.117(A59) J500.117(A59) JP3.2 R47.2 R607.2 R615.2 U7.10(2B1) U8.23(SDA) U14.3(SDA)
SDA_DDC_CI_1: J9.93(A47) J500.93(A47) U7.11(2B2)
SDA_DDC_CI_2: J9.114(B57) J500.114(B57) U7.12(2B3)
SDA_HDMI0_DDC_CI: CN1.16(DDC DATA) D517.1 R584.1 R591.1 U7.9(2A) U500.5(SDA)
SPDIF_DL2: J3.2 R605.1
SYSRSTN: R540.1 R542.1 U516.83(SYSRSTN)
UART_RX: J9.92(B46) J500.92(B46)
UART_TX: J9.53(A27) J500.53(A27)
VSYNC: R32.1 R568.1 U516.15(VSYNC)
WS_DR0_CONN: J3.12 R2.1
XTAL1: C680.1 U517.16(XTAL1) Y-1.2
XTAL2: C682.1 U517.15(XTAL2) Y-1.1
N17176927: C17.2 R29.1 U516.66(XTALOUT) X1.1
N17176943: C18.2 R29.2 U516.67(XTALIN) X1.2
N17208762: C679.1 R611.2 R612.1 U516.30(R0PWR5V)
N17213119: R11.2 U516.77(I2S3_DR2)
N17213121: R10.2 U516.76(I2S2_DL1)
N17213123: R9.2 U516.75(I2S1_DR1)
N17213125: R3.2 U516.73(I2S0_DL0)
N17213127: R2.2 U516.79(WS_DR0)
N17213129: R1.2 U516.80(SCK_DCLK)
N17216227: R606.2 U516.81(MCLK)
N17284357: R605.2 U516.71(SPDIF_DL2)
N17675272: R21.1 U516.102(QE26)
N17675274: R20.1 U516.101(QE27)
N17675276: RN1.9 U516.99(QE28)
N17675278: RN1.10 U516.98(QE29)
N17675280: RN1.11 U516.95(QE30)
N17675282: RN1.12 U516.94(QE31)
N17675284: RN1.13 U516.92(QE32)
N17675286: RN1.14 U516.91(QE33)
N17675288: RN1.15 U516.90(QE34)
N17675290: RN1.16 U516.89(QE35)
N17726793: R5.1 U516.27(R1PWR5V)
N17741544: R543.2 R544.2 U516.87(PCADR)
N17791476: R571.1 U516.16(EVENODD)
N17816955: R594.1 U516.85(SCDT)
N17949374: R541.1 U516.82(ENTEST)
N17950232: TP1.1(TP) U516.18(SIP_VDD)
N17950739: R595.2 U516.33(CBUS/HPD)
N17954990: R602.1 U516.20(CEC)
N17966004: D520.1(ANODE) R594.2
N18010922: RN2.10 U516.114(QE17)
N18010926: RN2.9 U516.115(QE16)
N18010974: R18.1 U516.117(QE15)
N18010978: R19.1 U516.118(QE14)
N18011121: RN2.11 U516.113(QE18)
N18011123: RN2.12 U516.112(QE19)
N18011125: RN2.13 U516.111(QE20)
N18011127: RN2.14 U516.108(QE21)
N18011129: RN2.15 U516.106(QE22)
N18011131: RN2.16 U516.105(QE23)
N18011461: RN4.10 U516.4(QE5)
N18011465: RN4.9 U516.5(QE4)
N18011513: R30.1 U516.7(QE3)
N18011517: R31.1 U516.8(QE2)
N18011660: RN4.11 U516.3(QE6)
N18011662: RN4.12 U516.2(QE7)
N18011664: RN4.13 U516.1(QE8)
N18011666: RN4.14 U516.126(QE9)
N18011668: RN4.15 U516.125(QE10)
N18011670: RN4.16 U516.124(QE11)
N18041897: C626.1 R586.1 R588.2 U512.5(FB)
N18041909: C624.1 C625.1 C626.2 L502.2 R586.2 R629.1
N28289603: L502.1 U512.3(SW)
N28326141: C681.2 R628.2 U517.5(RST)
N28326313: R621.1 U517.3(P1.6)
N28326316: R625.2 U517.32(V30)
N28326449: R620.1 U517.2(P1.5)
N28326927: R618.1 U517.43(T2.P1.0)
N28326930: R615.1 U517.44(T2EX.P1.1)
N28358514: R39.2 U516.70(DSD_DL3_3DR)
N28456981: C796.2 U518.6(VBST)
N28456983: C796.1 L503.1 U518.2(SW)
N28457010: C799.1 C800.2 C801.2 L503.2 R630.1 R633.1
N28457030: C799.2 R633.2 R634.1 U518.4(VFB)
N28459422: R635.1 U518.5(EN)
N270050601: Q500.2(BASE) R500.2

Pads without a net: CN1 14; J9 16 17 18 19 20 21 22 23 24 25 26 27 28 29 30 31 32 33 34 35 36 37 38 39 40 41 42 43 44 45 47 49 50 51 52 54 90 94 96 97 98 99 100 101 102 103 104 105 116 118; J500 16 17 18 19 20 21 22 23 24 25 26 27 28 29 30 31 32 33 34 35 36 37 38 39 40 41 42 43 44 45 47 49 50 51 52 54 90 94 96 97 98 99 100 101 102 103 104 105 116 118; U7 3 13; U8 1 8 9 10 11 13 14 15 16 17 18 19 20; U516 10 11 17 19 25 26 49 54 55 56 57 59 60 61 62 69 103 104 120 122; U517 1 4 7 10 11 13 14 18 20 21 22 23 24 25 26 27 28 29 30 31 33 34 35 36 42 45 46 47 48

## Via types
v1: diameter 0.61, hole 0.305, TOP to BOTTOM, 562 vias

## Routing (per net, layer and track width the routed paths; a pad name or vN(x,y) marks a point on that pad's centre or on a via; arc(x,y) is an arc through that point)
GND: length 253.6
  TOP w0.254: v1(30.35,47.37) 30.79,46.93 U516.119 ; U516.107 v1(25.99,47.29) ; U516.96 v1(22.01,46) ; v1(22.1,50.29) 21.8,50 U516.86 ; U516.31 38.44,58 v1(38.99,58.54) ; v1(17.43,55.6) U516.72
  TOP w0.267: v1(8.76,1.65) 9.54,1.64 ; J9.G2 v1(14.22,8) J9.G3 v1(20.57,8) J9.G4
  TOP w0.3: CN1.8 v1(39.54,78.25) ; CN1.17 44.04,78.06 v1(43.41,78.7) ; CN1.5 v1(38.04,78.25) ; CN1.11 v1(41.04,78.25) ; CN1.2 v1(36.54,78.25)
  TOP w0.381: U517.17 13.24,28.05 13.54,28.35 v1(13.54,28.79) ; C3.1 v1(58.37,50.79) ; C38.2 9.26,1.64 v1(8.76,1.65) 8.78,1.64 C37.2 ; C36.2 6.34,1.78 v1(5.59,1.78) ; D520.2 v1(9.87,38.59) ; R628.1 16.26,37.08 v1(16.13,37.21) ; v1(40.29,74.93) U511.8 U511.3 v1(40.29,72.54) ; U512.2 v1(31.48,21.91) ; v1(57.86,61.46) 57.16,62.16 C608.1 ; C508.1 v1(48.2,46.86) ; U7.8 v1(51.44,42.94) ; v1(37.29,72.54) U510.3 U510.8 v1(37.29,74.93) ; v1(4.19,8) J9.G1 ; J6.4 v1(54.15,37.56) ; U8.2 v1(46.18,36.34) ; U8.12 v1(44.51,28.84)
  TOP w0.508: 13.36,59.82 11.3,59.82 v1(10.24,58.76) ; C665.2 C664.2 C663.2 ; C623.2 v1(31.48,21.91) ; v1(11.99,52.78) 12.33,53.12 R541.2 ; J9.G4 J9.G5 v1(28.32,8) J9.G6 v1(34.54,8) J9.G7 v1(40.64,8) J9.G8 ; v1(16.41,70.66) 16.41,71.47 14.16,73.73 R634.2 ; v1(42.85,27.18) 42.85,28.77 41.64,29.98 29.68,29.98 29.09,29.39 R588.1 ; J9.G2 v1(8.38,8) J9.G1 ; C35.2 v1(11.02,13.66) ; C34.2 v1(6.39,13.66)
  TOP w0.762: v1(46.36,64.51) D517.3 v1(43.85,64.51) ; v1(47.62,60.31) C643.2 v1(46.06,61.86) ; 7.11,45.87 v1(6.2,45.87) ; 7.11,54.2 v1(6.17,54.2)
  BOTTOM w0.267: J9.G2 v1(14.22,8) J9.G3 v1(20.57,8) J500.G4
  BOTTOM w0.381: v1(57.86,61.46) 57.64,61.68 R574.2 ; v1(32.92,53.46) 33.02,53.56 C655.2 ; D519.3 v1(42.01,81.11) ; D519.3 v1(43.57,79.86) ; D519.3 v1(43.57,82.36) ; C680.2 v1(13.54,26.96) ; v1(5.59,1.78) 5.73,1.64 C36.2 ; J500.G4 J500.G5 v1(28.32,8) J9.G6 v1(34.54,8) J9.G7 v1(40.64,8) J500.G8 ; C5.1 v1(50.55,38.19) ; v1(4.19,8) J500.G1 v1(8.38,8) J9.G2 ; C682.2 v1(13.54,28.79) ; R543.1 v1(15.62,44.14)
  BOTTOM w0.508: C649.2 22.98,65.38 v1(22.48,65.88) ; v1(25.7,55.37) 25.62,55.29 C647.2 ; C632.2 35.15,47.17 C672.2 34.87,48.62 v1(34.11,48.62) v1(32.95,48.62) ; C673.2 38.46,53.24 v1(38.86,52.83) ; C661.2 25.55,58.83 v1(25.27,58.55) ; C668.2 16.64,47.02 R543.1 ; C662.2 13.84,66.04 v1(13.72,66.17) ; C35.2 v1(11.02,13.66) ; v1(22.01,46) 22,46 C633.2 ; v1(40,56.15) 39.63,56.52 R5.2 ; Q500.1 v1(44.85,43.97) ; v1(39.19,59.8) 38.44,59.8 R612.2 C679.2 38.23,57.78 v1(38.99,58.54) ; C653.2 31.65,59.69 C660.2 ; C683.2 v1(11.81,38.7) ; C34.2 v1(6.39,13.66) ; C38.2 9.77,1.65 v1(8.76,1.65) 7.76,1.65 C37.2 ; C677.2 21.08,60.22 v1(21.12,60.18) 21.29,60.01 C644.2 ; C606.2 54.84,61.85 v1(54.84,61.07) U505.3
  BOTTOM w0.762: C667.2 C637.2 C636.2 20.95,50.8 21.46,50.29 v1(22.1,50.29) ; C652.2 v1(37.95,62.87) ; v1(25.99,47.29) 26.31,46.97 C634.2 C638.2 24.99,44.35 25.43,43.92 C671.2 C669.2 ; 30.12,41.3 30.12,40.54 31.01,39.65 C628.2 ; 30.12,41.3 v1(31.03,41.3) ; 30.12,41.3 C670.2 ; v1(31.78,58.57) C660.2 C648.2 C678.2 ; C676.2 C650.2 25.43,59.94 C661.2 ; C629.2 11.2,55.6 C630.2 C631.2 14.91,56.41 16.62,56.41 v1(17.43,55.6) 18.34,56.51 20.61,56.51 C635.2 ; v1(30.35,47.37) 30.35,46.33 C639.2
  vias: v1(0.61,82.65) v1(0.61,80.31) v1(1.7,6.05) v1(1.96,18.26) v1(1.96,14.45) v1(2.13,43.84) v1(2.13,40.03) v1(2.13,36.22) v1(2.13,32.41) v1(2.26,84.3) v1(2.26,78.66) v1(2.87,4.61) v1(3.4,41.94) v1(3.4,38.13) v1(3.4,34.32) v1(4.6,84.3) v1(4.6,78.66) v1(6.25,82.65) v1(6.25,80.31) v1(9.78,66.44) v1(10.64,83.02) v1(11.48,9.04) v1(11.61,68.2) v1(11.85,72.24) v1(12.55,81.75) v1(12.85,1.73) v1(13.49,25.3) v1(14.45,83.02) v1(14.53,28.49) v1(14.48,27.18) v1(14.48,26.04) v1(14.48,24.89) v1(14.76,3) v1(15.86,27.31) v1(15.86,24.72) v1(16,28.45) v1(16,26.04) v1(16.36,81.75) v1(16.41,69.39) v1(16.41,68.12) v1(16.41,66.85) v1(16.41,42.79) v1(16.41,41.51) v1(16.66,1.73) v1(17.23,71.7) v1(18.26,83.02) v1(18.5,71.7) v1(19.77,72.97) v1(19.77,71.7) v1(20.17,81.75) v1(20.39,38.6) v1(20.47,1.73) v1(22.38,3) v1(23.5,6.83) v1(24.28,1.73) v1(25.35,48.92) v1(26.19,3) v1(27.15,55.65) v1(28.02,55.65) v1(28.09,1.73) v1(28.17,48.92) v1(29.69,83.02) v1(30.22,55.73) v1(31.34,48.92) v1(33,19.49) v1(33.25,20.55) v1(34.27,20.76) v1(34.27,19.49) v1(35.41,81.75) v1(35.71,1.73) v1(37.31,83.02) v1(37.39,6.93) v1(38.82,75.01) v1(38.82,72.62) v1(39.22,81.75) v1(39.52,1.73) v1(41.12,83.02) v1(41.43,3) v1(41.47,24.03) v1(42.85,25.91) v1(43.33,1.73) v1(44.12,27.18) v1(44.12,25.91) v1(45.87,15.06) v1(45.87,11.25) v1(45.87,7.44) v1(45.87,3.63) v1(47.14,16.97) v1(47.14,13.16) v1(47.14,9.35) v1(47.14,5.54) v1(47.14,1.73) v1(49.68,21.67) v1(49.68,19.33) v1(50.84,55.63) v1(50.84,54.36) v1(50.84,53.09) v1(50.84,51.95) v1(51.33,23.32) v1(51.33,17.68) v1(52.11,55.63) v1(52.11,54.36) v1(52.11,53.09) v1(52.11,51.95) v1(52.55,83.02) v1(53.67,23.32) v1(53.67,17.68) v1(54.26,82.65) v1(54.26,80.31) v1(55.12,55.87) v1(55.12,54.92) v1(55.32,21.67) v1(55.32,19.33) v1(55.92,84.3) v1(55.92,78.66) v1(55.98,55.39) v1(56.84,55.87) v1(56.84,54.92) v1(57.43,28.53) v1(57.43,24.72) v1(57.43,20.91) v1(57.93,56.73) v1(57.93,55.46) v1(57.93,54.19) v1(58.25,84.3) v1(58.25,78.66) v1(58.64,48.16) v1(58.64,46.89) v1(58.64,45.62) v1(58.64,44.35) v1(58.7,26.62) v1(58.7,22.81) v1(58.7,19) v1(59.9,82.65) v1(59.9,80.31)
P5V: length 5.8
  TOP w0.381: R575.1 56.89,63.87 v1(56.56,63.54) ; v1(44.58,72.87) D518.1 v1(45.8,72.07) ; U14.1 55.01,53.28
  TOP w0.508: 55.01,53.28 55.01,51.56 v1(54.5,51.05)
  vias: v1(11.16,16.68) v1(12.43,16.68) v1(12.43,15.41) v1(17.46,79.56) v1(17.46,78.29) v1(18.73,79.56) v1(18.73,78.29) v1(20,79.56) v1(20,78.29) v1(27.82,24.13) v1(27.82,22.86) v1(27.82,21.59) v1(29.09,24.13) v1(29.09,22.86) v1(29.09,21.59) v1(49.58,60.04) v1(49.59,59.07) v1(49.59,57.8) v1(50.68,81.81) v1(50.68,80.54) v1(50.68,79.27) v1(50.68,78) v1(50.68,76.73) v1(50.68,75.46) v1(50.85,60.04) v1(50.86,59.07) v1(51.95,81.81) v1(51.95,80.54) v1(51.95,79.27) v1(51.95,78) v1(52.22,57.95)
P5V_HDMI0: length 36.3
  TOP w0.635: R585.2 v1(43.16,70.08) ; v1(46.83,70.08) R584.2 45.96,70.63 47.23,71.9 D518.3
  05_SIG2 w0.635: v1(46.83,70.08) v1(43.16,70.08) 42.65,70.08 40.7,68.12 40.7,57.44 48.16,49.98 48.16,49.13 v1(48.72,48.56) v1(49.99,48.56)
P5V_LAB:
  vias: v1(54.87,77.2) v1(54.87,75.93) v1(54.87,74.66) v1(56.14,77.2) v1(56.14,75.93) v1(56.14,74.66) v1(57.41,77.2) v1(57.41,75.93) v1(58.68,77.2) v1(58.68,75.93)
P5V_MAIN: length 9.2
  TOP w0.305: J9.11 9.75,12.35 v1(9.53,12.57) 9.25,12.3 J9.9
  TOP w0.508: C35.1 9.28,12.81 v1(9.53,12.57)
  BOTTOM w0.267: J500.9 9.25,12.3 v1(9.53,12.57) 9.75,12.35 J500.11
  BOTTOM w0.508: C35.1 9.28,12.81 v1(9.53,12.57)
  vias: v1(8.41,16.19) v1(8.41,14.92)
51_SCL: length 26.4
  TOP w0.267: U517.6 16.65,32.5 16.26,32.89 v1(15.62,32.89) 14.73,33.78 R622.1
  BOTTOM w0.267: JP2.1 4.79,24.22 4.79,31.32 5.85,32.38 10.17,32.38 11.23,31.32 14.05,31.32 v1(15.62,32.89)
51_SDA: length 24.6
  TOP w0.267: v1(15.11,30.1) 15.63,30.62 U517.8 ; JP2.3 3.15,17.5 R623.1 v1(5.08,21.03)
  05_SIG2 w0.102: v1(5.08,21.03) 9.69,21.03 12.44,23.78 12.44,28.92 13.62,30.1 v1(15.11,30.1)
AFE_RSTZ: length 133.5
  TOP w0.267: R542.2 12.06,50.2 11.8,50.47 v1(11.8,50.5) ; v1(42.9,35.69) U8.3 ; U517.12 13.63,32.08 13.34,32.37 v1(12.84,32.37) ; v1(38.75,2.32) J9.108
  03_SIG1 w0.147: v1(42.9,35.69) 41.92,34.71 41.92,29.48 40.61,28.17 40.61,16.44 38.16,13.99 38.16,3.85 38.75,3.26 v1(38.75,2.32)
  05_SIG2 w0.102: v1(38.75,2.32) 36.92,2.32 34.81,4.43 14.74,4.43 7.32,11.86 7.32,16.39 4.11,19.59 4.11,21.71 5.31,22.91 8.86,22.91 11.48,25.52 11.48,30.35 12.84,31.71 v1(12.84,32.37) 10.57,32.37 7.23,35.71 7.23,47.19 10.2,50.17 11.44,50.17 11.77,50.5 v1(11.8,50.5)
  BOTTOM w0.267: v1(38.75,2.32) J500.108 ; R624.1 v1(11.8,50.5)
ALT_PWR: length 5.6
  TOP w0.305: J9.1 6.73,11.09
  TOP w0.381: 6.73,11.09 6.4,11.42 4.31,11.42 3.35,10.46 R56.1
ALT_PWR2: length 9.1
  TOP w0.267: v1(2.79,8) 3.56,8.76 6.99,8.76 7.75,9.53 J9.3
  BOTTOM w0.267: v1(2.79,8) 2.29,8.51 R583.1
ALT_PWR2_MCONN: length 8.9
  BOTTOM w0.267: R583.2 3.51,10.41 3.51,9.7 4.45,8.76 7.24,8.76 7.75,9.27 J500.3
ALT_PWR_MCONN: length 6.3
  TOP w0.267: R56.2 v1(4.86,12.4)
  BOTTOM w0.267: v1(4.86,12.4) 6.76,12.4 7.25,11.91 J500.1
BUS_SELECT: length 67.8
  TOP w0.267: v1(11.37,51.48) 11.54,51.66 R540.2 ; v1(18.54,15.78) 31.67,15.78 33.91,13.54 v1(33.91,12.57) 34.25,12.23 J9.89
  05_SIG2 w0.102: v1(11.37,51.48) 12.07,51.48 12.53,51.02 12.53,49.99 12.23,49.68 10.29,49.68 8.24,47.63 8.24,38.36 9.9,36.7 10.96,36.7 14.25,33.41 14.25,33.12 15.22,32.14 16.47,32.14 18.68,29.93 18.68,15.92 v1(18.54,15.78)
  BOTTOM w0.267: v1(33.91,12.57) 34.25,12.23 J500.89
CEC: length 42.1
  TOP w0.267: v1(45.88,82.86) 45.29,82.86 42.04,79.61 CN1.13 ; v1(44.81,55.86) R602.2 R601.1
  BOTTOM w0.267: v1(44.81,55.86) 44.81,66.85 49.34,71.38 49.34,79.54 46.92,81.97 D519.1 v1(45.88,82.86)
DDCSCL0: length 11.5
  TOP w0.267: R589.2 40.33,62.72 40.33,58.89 38.64,57.2 U516.29
DDCSDA0: length 17.1
  TOP w0.267: U516.28 39.28,56.8 41.14,58.66 41.14,61.98 41.81,62.64 46.56,62.64 47.54,63.62 R591.2
DE: length 6.9
  TOP w0.267: U516.12 38.39,50.4 39.37,49.42 41.71,49.42 42.05,49.07 R570.1
HAPS_CLK: length 5.1
  TOP w0.267: v1(42.78,13.1) 41.75,12.08 J9.119
  BOTTOM w0.267: v1(42.78,13.1) 41.75,12.08 J500.119
HDMI_0_VCC5: length 22.2
  TOP w0.267: CN1.18 v1(44.54,74.92) 44.54,74.01 D518.2
  05_SIG2 w0.102: v1(44.54,74.92) 38.73,69.12 38.73,61.37 v1(39.02,61.09)
  BOTTOM w0.267: v1(44.54,74.92) 44.17,75.3 R590.1 ; R611.1 v1(39.02,61.09)
HDMI_CEC: length 78.2
  TOP w0.267: v1(12.42,13.21) 12.16,12.95 10.94,12.95 10.25,12.26 J9.13 ; R601.2 v1(49.51,54.74)
  03_SIG1 w0.147: v1(49.51,54.74) 48.63,53.86 42.07,53.86 41.46,53.24 41.46,53.01 40.19,51.75 40.19,42.36 36,38.17 28.61,38.17 26.61,36.18 26.61,31.5 26.88,31.23 26.88,29.87 26.53,29.51 26.53,26.6 23.8,23.88 23.8,17.59 21.29,15.07 14.28,15.07 v1(12.42,13.21)
  BOTTOM w0.267: v1(12.42,13.21) 12.09,12.88 10.87,12.88 10.25,12.26 J500.13
HDMI_DDC_CI_OEZ: length 31.4
  TOP w0.267: v1(55.77,48.52) 56.43,47.86 U7.15 ; U7.1 51.44,49.14 51.58,49.29 R15.2 v1(51.58,51.01) ; U8.6 v1(46.16,33.74)
  05_SIG2 w0.102: v1(51.58,51.01) 51.88,51.31 52.98,51.31 v1(55.77,48.52) 55.42,48.17 55.07,48.17 52.44,45.54 52.44,43.06 51.07,41.69 50.52,41.69 45.4,36.57 45.4,34.49 v1(46.16,33.74)
HDMI_DDC_CI_S0: length 19.7
  TOP w0.267: U7.14 55.96,47.21 v1(55.85,47.33) ; v1(46.11,35.04) U8.4
  05_SIG2 w0.102: v1(46.11,35.04) 47.81,36.73 47.81,37.39 53.22,42.8 53.22,45.05 55.5,47.33 v1(55.85,47.33)
HDMI_DDC_CI_S1: length 24.6
  TOP w0.267: U7.2 52.65,47.86 53.71,48.92 v1(53.71,49.7) ; v1(43.11,34.39) U8.5
  05_SIG2 w0.102: v1(43.11,34.39) 44.31,35.59 44.31,36.1 50.74,42.53 50.74,45.08 53.71,48.05 v1(53.71,49.7)
HDMI_EDID_WEZ: length 11.2
  TOP w0.267: v1(46.89,32.37) 46.17,32.37 45.45,33.09 U8.7
  BOTTOM w0.267: R500.1 47.32,40.25 47.32,32.79 v1(46.89,32.37)
HDMI_EDID_WP: length 7.4
  BOTTOM w0.267: Q500.3 48.16,45.77 49.26,46.87 R509.2 U500.7
HDMI_INT: length 106.4
  TOP w0.267: v1(35.69,9.09) 34.75,10.03 J9.91 ; R593.1 13.34,33.43 v1(13.41,33.36) 14.22,33.36 15.15,32.43 U517.9 ; U516.21 39.43,54 39.87,53.55 v1(40.3,53.55)
  03_SIG1 w0.147: v1(40.3,53.55) 40.3,53.41 38.77,51.88 38.77,42.54 35.38,39.15 26.43,39.15 23.94,36.67 23.94,35.42 22.21,33.69 13.74,33.69 v1(13.41,33.36)
  05_SIG2 w0.102: v1(13.41,33.36) 16.04,30.72 16.04,29.65 15.17,28.78 15.17,8.22 18.21,5.18 34.98,5.18 36.12,6.33 36.12,8.66 v1(35.69,9.09)
  BOTTOM w0.267: v1(35.69,9.09) 35.38,9.4 34.9,9.4 34.75,9.55 J500.91
HSYNC: length 11
  TOP w0.267: U516.14 38.91,51.2 39.96,50.15 44.31,50.15 44.81,50.65 R572.1 R569.1
I2S0_DL0_CONN: length 2.6
  TOP w0.267: R3.1 J3.10
I2S1_DR1_CONN: length 2.6
  TOP w0.267: R9.1 J3.8
I2S2_DL1_CONN: length 2.6
  TOP w0.267: R10.1 J3.6
I2S3_DR2_CONN: length 2.6
  TOP w0.267: R11.1 J3.4
I2S_SCK_CONN: length 4.2
  TOP w0.267: R606.1 R1.1 4.95,60.2 J3.14
NC1: length 3.6
  TOP w0.267: J9.48 v1(18.75,3.23)
  BOTTOM w0.267: J500.48 v1(18.75,3.23)
NC2: length 4.5
  TOP w0.267: J9.106 38.25,3.59 v1(37.68,3.03)
  BOTTOM w0.267: J500.106 38.25,3.59 v1(37.68,3.03)
NC3: length 3.6
  TOP w0.267: J9.107 v1(38.75,9.19)
  BOTTOM w0.267: J500.107 v1(38.75,9.19)
NC4: length 4.2
  TOP w0.267: v1(38.88,12.94) 39.25,12.57 J9.109
  BOTTOM w0.267: v1(38.88,12.94) 39.25,12.57 J500.109
NC5: length 4.1
  TOP w0.267: v1(38.99,6.99) 39.25,6.73 J9.110
  BOTTOM w0.267: J500.110 39.25,6.73 v1(38.99,6.99)
NC6: length 6.4
  TOP w0.267: J9.111 39.75,13.4 v1(39.19,13.96)
  BOTTOM w0.267: v1(39.19,13.96) 39.75,13.4 J500.111
NC7: length 3.1
  TOP w0.267: J9.112 v1(39.75,3.45)
  BOTTOM w0.267: v1(39.75,3.45) J500.112
NC8: length 4
  TOP w0.267: J9.120 41.75,3.97 v1(42.42,3.3)
  BOTTOM w0.267: v1(42.42,3.3) 41.75,3.97 J500.120
P0.0: length 5.6
  TOP w0.267: v1(17.99,27.15) 17.99,26.71 18.66,26.05 U517.40
  BOTTOM w0.267: v1(17.99,27.15) 17.99,26.71 19.2,25.5 R614.2
P0.1: length 8.7
  TOP w0.267: v1(16.89,26.8) 18.12,25.57 U517.39
  BOTTOM w0.267: R619.2 19.08,23.89 18.2,24.77 18.2,25.49 v1(16.89,26.8)
P0.2: length 6.3
  TOP w0.267: v1(17.14,25.53) 17.14,25.45 17.54,25.06 U517.38
  BOTTOM w0.267: R616.2 17.61,23.46 17.61,25.06 v1(17.14,25.53)
P0.3: length 5.4
  TOP w0.267: U517.37 17.01,24.55 v1(16.89,24.42)
  BOTTOM w0.267: R617.2 15.9,23.43 v1(16.89,24.42)
P1_A0: length 36.4
  TOP w0.267: J9.65 28.25,9.45 27.59,8.8 v1(26.72,8.8) ; v1(23.23,35.92) 23.3,35.99 23.3,36.79 R21.2
  05_SIG2 w0.102: v1(23.23,35.92) 23.23,33.69 23.8,33.12 23.8,26.11 25.14,24.77 25.14,20.04 25.65,19.53 25.65,10.67 26.29,10.03 26.29,9.23 v1(26.72,8.8)
  BOTTOM w0.267: v1(26.72,8.8) 27.58,8.8 28.25,9.46 J500.65
P1_A1: length 39.7
  TOP w0.267: J9.64 27.75,6.36 27.49,6.62 26.45,6.62 v1(26.09,6.99) ; R20.2 21.7,37.26 v1(21.2,37.26)
  05_SIG2 w0.102: v1(26.09,6.99) 25.78,7.29 25.78,9.78 25.15,10.41 25.15,19.24 24.63,19.76 24.63,24.65 23.39,25.88 23.39,32.92 22.77,33.55 22.77,35.19 22.35,35.61 22.35,36.1 v1(21.2,37.26)
  BOTTOM w0.267: v1(26.09,6.99) 26.43,6.64 27.46,6.64 27.75,6.36 J500.64
